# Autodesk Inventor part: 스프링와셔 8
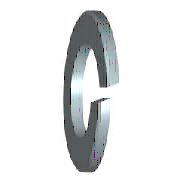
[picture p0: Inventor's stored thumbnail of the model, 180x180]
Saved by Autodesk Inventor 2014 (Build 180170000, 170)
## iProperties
IsCustomPart: 1
Created: 2012-02
Part Number: 스프링와셔 8
Material: 강철, 연강
Description: 스프링 잠금 와셔
Document SubType Name: Modeling
Standard: KS B 1324
Designer: mduedu
Standards Organization: KS
Language: ko-KR
Size Designation: 번호 3 - 8
Categories: <MemberInstance><Categories><Category DisplayName="조임쇠" InternalName="e4da775c-781d-43d5-af7c-5136215cf5a6" Mnemonic="FSTN"><Category DisplayName="와셔" InternalN
Density: 7.86 g/cm^3
Mass: 2.27751 g
Surface Area: 4.25113 cm^2
Volume: 0.289759 cm^3
Appearance: 파란색 - 벽 페인트 - 광택
Author: mduedu
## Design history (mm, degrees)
sketch "스케치1"
  geometry: C1 r 7.4 at (0, 0); C2 r 4.1 at (0, 0); 1 further point
  constraints: 2 centre point, 2 coincident
  dimensions: "d0" = 8.2 diameter of C2 (= SD1); "d1" = 14.8 diameter of C1 (= SD2)
extrude "본체" new body sketch "스케치1" distance "d2" = 2.5 (= SD); taper "d3" = 0 deg
sketch "스케치2"
  geometry: L1 (0, -4.1)-(0, 4.1) reference; L2 (2.5, 7.4)-(2.5, -7.4) reference; L3 (-1.2, 0)-(7.2, 0) reference; L4 (0, -0.5)-(2.5, 0.41); L5 (0, 0.5)-(2.5, 1.41)
  constraints: 4 end point, 4 point on line, 1 parallel
  dimensions: "d4" = 0.5 distance from line of L3 L4.start (= 0.2 x SD); "d5" = 0.5 distance from line of L3 L5.start (= 0.2 x SD); "d6" = 70 deg angle of L2 L4 (= FAWI)
extrude "절단부" cut sketch "스케치2" stored distance "d7" = 2.5 (= SD); taper "d8" = 0 deg
workaxis "Work Axis1"
workplane "Work Plane1"
body "Solid1"
other parameters: "SD1" = 8.2 [user parameter; used in 1 equation term], "SD2" = 14.8 [user parameter; used in 1 equation term], "SD" = 2.5 [user parameter; used in 4 equation terms], "FAWI" = 70 deg [user parameter; used in 1 equation term], "d9" = 0, "d10" = 0, "d11" = 0, "d12" = 0, "SDI" = 3.3 [user parameter], "NND" = 8 [user parameter]
